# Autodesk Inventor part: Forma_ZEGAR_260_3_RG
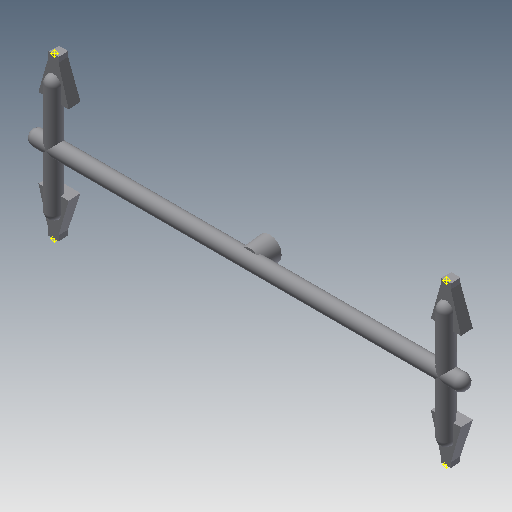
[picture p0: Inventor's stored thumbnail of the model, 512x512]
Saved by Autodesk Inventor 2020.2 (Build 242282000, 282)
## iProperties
Created: 2015-01
Part Number: Forma_ZEGAR_260_3_RG
Material: Ogólny
Document SubType Name: Modeling
Designer: F.Stasiak
Density: 1 g/cm^3
Appearance: Domyślna
Catalog Web Link: www.expertbooks.pl
Manager: www.cadconsulting.pl
Company: Fabian Stasiak CAD Consulting
Author: F.Stasiak
Subject: Zbiór ćwiczeń. Autodesk Inventor 2020. Kurs Professional
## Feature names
1. Wyciągnięcie proste7 [Extrusion]
2. Przeciągnięcie1
3. Obrót1 [Revolution]
4. Wyciągnięcie proste1 [Extrusion]
5. Przeciągnięcie2
6. Obrót2 [Revolution]
7. Wyciągnięcie proste2 [Extrusion]
8. Przeciągnięcie3
9. Obrót3 [Revolution]
10. Wyciągnięcie proste3 [Extrusion]
11. Przeciągnięcie4
12. Obrót4 [Revolution]
13. Wyciągnięcie proste4 [Extrusion]
14. Przeciągnięcie5
15. Obrót5 [Revolution]
16. Wyciągnięcie proste5 [Extrusion]
17. Przeciągnięcie6
18. Obrót6 [Revolution]
19. Wyciągnięcie proste6 [Extrusion]
20. Wyciągnięcie złożone1
21. Wyciągnięcie złożone2
22. Wyciągnięcie złożone3
23. Wyciągnięcie złożone4
## Parameters: d0 = -9.8085 mm, d1 = 39 mm, d2 = 8 mm, d3 = 3 mm, d4 = 0, d5 = 0, d6 = -3 mm, d7 = 3 mm, d8 = 180 deg, d9 = 3 mm, d10 = 3 mm, d11 = 0, d12 = 3 mm, d13 = 0, d14 = 0, d15 = 3 mm, d16 = 3 mm, d17 = 180 deg, d18 = 3 mm, d19 = 3 mm, d20 = 0, d21 = 3 mm, d22 = 0, d23 = 0, d24 = -3 mm, d25 = 3 mm, d26 = 180 deg, d27 = 3 mm, d28 = 3 mm, d29 = 0, d30 = 3 mm, d31 = 0, d32 = 0, d33 = 3 mm, d34 = 3 mm, d35 = 180 deg, d36 = 3 mm, d37 = 3 mm, d38 = 0, d39 = 3 mm, d40 = 0, d41 = 0, d42 = 3 mm, d43 = 3 mm, d44 = 180 deg, d45 = 3 mm, d46 = 3 mm, d47 = 0, d48 = 3 mm, d49 = 0, d50 = 0, d51 = 3 mm, d52 = 3 mm, d53 = 180 deg, d54 = 3 mm, d55 = 3 mm, d56 = 0, d57 = 1 mm, d58 = 2 mm, d59 = 2 mm, d60 = 87 deg, d61 = 87 deg, d62 = 6 mm, d63 = 2.5 mm, d64 = 87 deg, d65 = 87 deg, d66 = 0, d67 = 90 deg, d68 = 0, d69 = 90 deg, d70 = 1 mm, d71 = 1 mm, d72 = 2 mm, d73 = 2 mm, d74 = 87 deg, d75 = 87 deg, d76 = 6 mm, d77 = 2.5 mm, d78 = 87 deg, d79 = 87 deg, d80 = 0, d81 = 90 deg, d82 = 0, d83 = 90 deg, d84 = 1 mm, d85 = 1 mm, d86 = 2 mm, d87 = 2 mm, d88 = 87 deg, d89 = 87 deg, d90 = 6 mm, d91 = 2.5 mm, d92 = 87 deg, d93 = 87 deg, d94 = 0, d95 = 90 deg, d96 = 0, d97 = 90 deg, d98 = 1 mm, d99 = 1 mm, d100 = 2 mm, d101 = 2 mm, d102 = 87 deg, d103 = 87 deg, d104 = 6 mm, d105 = 2.5 mm, d106 = 87 deg, d107 = 87 deg, d108 = 0, d109 = 90 deg, d110 = 0, d111 = 90 deg, d112 = 1 mm, d113 = 4 mm, d114 = 5 deg
